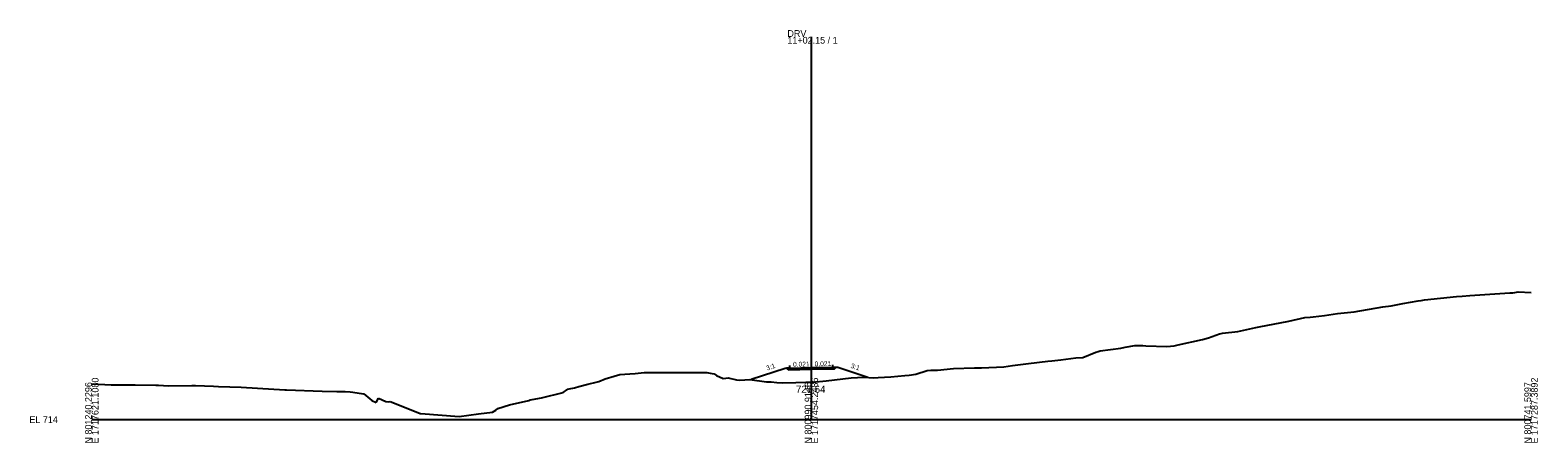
# Model space of a CAD drawing. Extents: x -26 to 603, y -10 to 3134.
# Drawn here: x -26 to 603, y 1990 to 2162 of the extents above; entities that cross this region are included whole.
import ezdxf

# ---------------------------------------------------------------- set-up
doc = ezdxf.new("R2010")
doc.units = 0
for name, color, linetype in [('Exist Cross Section Cell', 7, 'Continuous'), ('Exist XS Center Line Elevation Label', 7, 'Continuous'), ('Exist XS Ground Line', 7, 'Continuous'), ('Prop XS Dump Level', 7, 'Continuous'), ('Prop XS EOT Tick Mark', 7, 'Continuous'), ('Prop XS Finish Grade', 7, 'Continuous'), ('Prop XS Finish Grade Earthwork', 7, 'Continuous'), ('Prop XS Finish Grade Pavement', 7, 'Continuous'), ('Prop XS Pvmt Edge Slope', 7, 'Continuous'), ('Prop XS SE Text', 7, 'Continuous'), ('Prop XS Side Slope Text', 7, 'Continuous'), ('Prop XS Subgrade Earthwork', 7, 'Continuous')]:
    doc.layers.add(name, color=color, linetype=linetype)

msp = doc.modelspace()

# ---------------------------------------------------------------- linework, layer by layer
at = {"layer": 'Exist Cross Section Cell'}
for p, q in [((300, 2000), (300, 2159.44)), ((0, 2000), (300, 2000)), ((300, 2000), (600, 2000))]:
    msp.add_line(p, q, dxfattribs=at)
at = {"layer": 'Exist XS Ground Line'}
for p, q in [((546.57, 2048.38), (552.97, 2049.44)), ((552.97, 2049.44), (554.25, 2049.59)), ((554.25, 2049.59), (555.52, 2049.85)), ((555.52, 2049.85), (568.94, 2051.21)), ((568.94, 2051.21), (571.31, 2051.42)), ((571.31, 2051.42), (574.44, 2051.68)), ((574.44, 2051.68), (591.15, 2052.77)), ((591.15, 2052.77), (592.46, 2052.85)), ((592.46, 2052.85), (593.3, 2052.95)), ((593.3, 2052.95), (594.59, 2053.15)), ((594.59, 2053.15), (600, 2052.96)), ((507.97, 2042.68), (509.14, 2042.83)), ((509.14, 2042.83), (513.83, 2043.36)), ((513.83, 2043.36), (519.38, 2044.15)), ((519.38, 2044.15), (526.32, 2044.83)), ((526.32, 2044.83), (538.26, 2046.92)), ((538.26, 2046.92), (541.73, 2047.38)), ((541.73, 2047.38), (546.57, 2048.38)), ((471.37, 2035.96), (477.76, 2036.75)), ((477.76, 2036.75), (485.34, 2038.35)), ((485.34, 2038.35), (485.98, 2038.47)), ((485.98, 2038.47), (486.71, 2038.64)), ((486.71, 2038.64), (499.02, 2041.03)), ((499.02, 2041.03), (505.76, 2042.55)), ((505.76, 2042.55), (507.97, 2042.68)), ((429.03, 2029.76), (430.76, 2030.21)), ((430.76, 2030.21), (434.87, 2030.87)), ((434.87, 2030.87), (438.16, 2030.8)), ((438.16, 2030.8), (439.37, 2030.67)), ((439.37, 2030.67), (448.15, 2030.48)), ((448.15, 2030.48), (451.16, 2030.73)), ((451.16, 2030.73), (452.9, 2031.14)), ((452.9, 2031.14), (463.05, 2033.32)), ((463.05, 2033.32), (465.48, 2034.12)), ((465.48, 2034.12), (470.19, 2035.72)), ((470.19, 2035.72), (470.79, 2035.83)), ((470.79, 2035.83), (471.37, 2035.96)), ((390.48, 2023.33), (398.55, 2024.35)), ((398.55, 2024.35), (400.25, 2024.42)), ((400.25, 2024.42), (404.01, 2024.88)), ((404.01, 2024.88), (410.29, 2025.68)), ((410.29, 2025.68), (413.18, 2025.89)), ((413.18, 2025.89), (418.58, 2028.06)), ((418.58, 2028.06), (419.5, 2028.38)), ((419.5, 2028.38), (420.36, 2028.7)), ((420.36, 2028.7), (429.03, 2029.76)), ((214.06, 2016.94), (217.83, 2018.12)), ((217.83, 2018.12), (220.12, 2018.8)), ((220.12, 2018.8), (224.28, 2019.01)), ((224.28, 2019.01), (226.47, 2019.18)), ((226.47, 2019.18), (230.22, 2019.63)), ((230.22, 2019.63), (239.51, 2019.62)), ((239.51, 2019.62), (242.22, 2019.61)), ((242.22, 2019.61), (247.12, 2019.61)), ((247.12, 2019.61), (253.08, 2019.62)), ((253.08, 2019.62), (254.21, 2019.62)), ((254.21, 2019.62), (256.44, 2019.63)), ((256.44, 2019.63), (257.77, 2019.32)), ((257.77, 2019.32), (259.45, 2019.04)), ((259.45, 2019.04), (260.37, 2018.29)), ((260.37, 2018.29), (263.18, 2017.16)), ((316.51, 2017.34), (321.84, 2017.73)), ((321.84, 2017.73), (325.84, 2017.44)), ((327.82, 2017.5), (333.09, 2017.84)), ((333.09, 2017.84), (339.01, 2018.29)), ((339.01, 2018.29), (340.72, 2018.47)), ((340.72, 2018.47), (343.52, 2018.96)), ((343.52, 2018.96), (348.19, 2020.44)), ((348.19, 2020.44), (349.81, 2020.61)), ((349.81, 2020.61), (352.59, 2020.6)), ((352.59, 2020.6), (359.2, 2021.27)), ((359.2, 2021.27), (368, 2021.61)), ((368, 2021.61), (370.92, 2021.51)), ((370.92, 2021.51), (380.15, 2021.98)), ((380.15, 2021.98), (383.78, 2022.47)), ((383.78, 2022.47), (390.48, 2023.33)), ((0, 2014.85), (8.05, 2014.41)), ((8.05, 2014.41), (16.21, 2014.47)), ((8.05, 2014.41), (8.05, 2014.41)), ((8.05, 2014.41), (8.05, 2014.41)), ((8.05, 2014.41), (8.05, 2014.41)), ((16.21, 2014.47), (18.13, 2014.47)), ((18.13, 2014.47), (26.69, 2014.39)), ((26.69, 2014.39), (26.89, 2014.38)), ((26.89, 2014.38), (27.8, 2014.33)), ((27.8, 2014.33), (32.02, 2014.07)), ((32.02, 2014.07), (41.76, 2014.23)), ((41.76, 2014.23), (42.74, 2014.24)), ((42.74, 2014.24), (43.29, 2014.22)), ((43.29, 2014.22), (50.8, 2013.96)), ((50.8, 2013.96), (52.85, 2013.8)), ((52.85, 2013.8), (62.21, 2013.55)), ((62.21, 2013.55), (69.14, 2013.14)), ((69.14, 2013.14), (80.43, 2012.37)), ((80.43, 2012.37), (80.88, 2012.34)), ((80.88, 2012.34), (81.15, 2012.34)), ((81.15, 2012.34), (96.04, 2011.89)), ((96.04, 2011.89), (102.11, 2011.73)), ((102.11, 2011.73), (105.57, 2011.69)), ((105.57, 2011.69), (107.71, 2011.5)), ((107.71, 2011.5), (108.88, 2011.39)), ((108.88, 2011.39), (113.3, 2010.69)), ((196.57, 2011.28), (198.06, 2012.4)), ((198.06, 2012.4), (198.44, 2012.66)), ((198.44, 2012.66), (198.97, 2012.82)), ((198.97, 2012.82), (201.3, 2013.28)), ((201.3, 2013.28), (203.08, 2013.77)), ((203.08, 2013.77), (206.78, 2014.77)), ((206.78, 2014.77), (210.26, 2015.57)), ((210.26, 2015.57), (211.4, 2015.89)), ((211.4, 2015.89), (214.06, 2016.94)), ((263.18, 2017.16), (264.26, 2017.24)), ((264.26, 2017.24), (265.29, 2017.39)), ((265.29, 2017.39), (268.72, 2016.61)), ((268.72, 2016.61), (270.1, 2016.41)), ((270.1, 2016.41), (274.27, 2016.73)), ((274.27, 2016.73), (281.32, 2015.72)), ((281.32, 2015.72), (282.31, 2015.67)), ((282.31, 2015.67), (283.2, 2015.68)), ((283.2, 2015.68), (285.56, 2015.5)), ((285.56, 2015.5), (287.98, 2015.3)), ((287.98, 2015.3), (293.5, 2015.45)), ((293.5, 2015.45), (297.62, 2015.64)), ((297.62, 2015.64), (300, 2015.64)), ((300, 2015.64), (300.47, 2015.64)), ((300.47, 2015.64), (306.21, 2016.09)), ((306.21, 2016.09), (316.51, 2017.34)), ((325.84, 2017.44), (327.82, 2017.5)), ((113.3, 2010.69), (113.45, 2010.67)), ((113.45, 2010.67), (116.74, 2007.97)), ((116.74, 2007.97), (118.57, 2007.14)), ((118.57, 2007.14), (119.51, 2008.89)), ((119.51, 2008.89), (122.53, 2007.47)), ((122.53, 2007.47), (123.69, 2007.37)), ((123.69, 2007.37), (124.33, 2007.48)), ((124.33, 2007.48), (136.58, 2002.63)), ((169.25, 2004.63), (174.08, 2006.19)), ((174.08, 2006.19), (182.24, 2008)), ((182.24, 2008), (182.71, 2008.16)), ((182.71, 2008.16), (183.54, 2008.39)), ((183.54, 2008.39), (187.44, 2009.11)), ((187.44, 2009.11), (196.57, 2011.28)), ((136.58, 2002.63), (136.83, 2002.58)), ((136.83, 2002.58), (137.12, 2002.55)), ((137.12, 2002.55), (153.19, 2001.31)), ((153.19, 2001.31), (161.23, 2002.36)), ((161.23, 2002.36), (167.07, 2003.02)), ((167.07, 2003.02), (168.49, 2003.96)), ((168.49, 2003.96), (169.25, 2004.63))]:
    msp.add_line(p, q, dxfattribs=at)
at = {"layer": 'Prop XS Dump Level'}
for p, q in [((291, 2021.48), (300, 2021.66)), ((300, 2021.66), (309, 2021.85))]:
    msp.add_line(p, q, dxfattribs=at)
at = {"layer": 'Prop XS EOT Tick Mark'}
for p, q in [((291, 2021.48), (291, 2022.48)), ((309, 2021.85), (309, 2022.85))]:
    msp.add_line(p, q, dxfattribs=at)
at = {"layer": 'Prop XS Finish Grade'}
for p, q in [((291, 2021.48), (289.66, 2021.37)), ((309, 2021.85), (310.34, 2021.8))]:
    msp.add_line(p, q, dxfattribs=at)
at = {"layer": 'Prop XS Finish Grade Earthwork'}
for p, q in [((289, 2021.32), (274.95, 2016.63)), ((289.66, 2021.37), (289, 2021.32)), ((310.34, 2021.8), (311, 2021.77)), ((311, 2021.77), (323.47, 2017.62))]:
    msp.add_line(p, q, dxfattribs=at)
at = {"layer": 'Prop XS Finish Grade Pavement'}
for p, q in [((291, 2021.48), (300, 2021.66)), ((300, 2021.66), (309, 2021.85))]:
    msp.add_line(p, q, dxfattribs=at)
at = {"layer": 'Prop XS Pvmt Edge Slope'}
for p, q in [((291, 2021.48), (290.28, 2020.75)), ((309, 2021.85), (309.69, 2021.16))]:
    msp.add_line(p, q, dxfattribs=at)
at = {"layer": 'Prop XS Subgrade Earthwork'}
for p, q in [((290.28, 2020.75), (289.66, 2021.37)), ((290.28, 2020.75), (300.01, 2020.96)), ((300.01, 2020.96), (309.69, 2021.16)), ((309.69, 2021.16), (310.34, 2021.8))]:
    msp.add_line(p, q, dxfattribs=at)

# ---------------------------------------------------------------- texts
at = {"layer": 'Exist Cross Section Cell'}
for s, p in [('DRV', (290, 2159.44)), ('11+02.15 / 1', (290, 2156.64)), ('EL 714', (-26, 1998.6))]:
    msp.add_text(s, height=2.8, dxfattribs=at).set_placement(p)
for s, p in [('N 801240.2296', (0, 1990)), ('E 1717621.1080', (2.8, 1990)), ('N 800990.9146', (300, 1990)), ('E 1717454.2486', (302.8, 1990)), ('N 800741.5997', (600, 1990)), ('E 1717287.3892', (602.8, 1990))]:
    msp.add_text(s, height=2.8, rotation=90, dxfattribs=at).set_placement(p)
at = {"layer": 'Exist XS Center Line Elevation Label'}
msp.add_text('729.64', height=3, dxfattribs=at).set_placement((293.57, 2011.14))
at = {"layer": 'Prop XS Dump Level'}
for p in [(289, 2021.28), (311, 2021.73)]:
    msp.add_text('Case1', height=0.04, dxfattribs=at).set_placement(p)
at = {"layer": 'Prop XS SE Text'}
for p in [(292.36, 2022.01), (301.36, 2022.19)]:
    msp.add_text('0.021', height=2, rotation=1.19009, dxfattribs=at).set_placement(p)
at = {"layer": 'Prop XS Side Slope Text'}
for rotation, p in [(18.43495, (281.5, 2020.4)), (341.56505, (316.18, 2021.63))]:
    msp.add_text('3:1', height=2, rotation=rotation, dxfattribs=at).set_placement(p)

doc.saveas('drawing.dxf')
